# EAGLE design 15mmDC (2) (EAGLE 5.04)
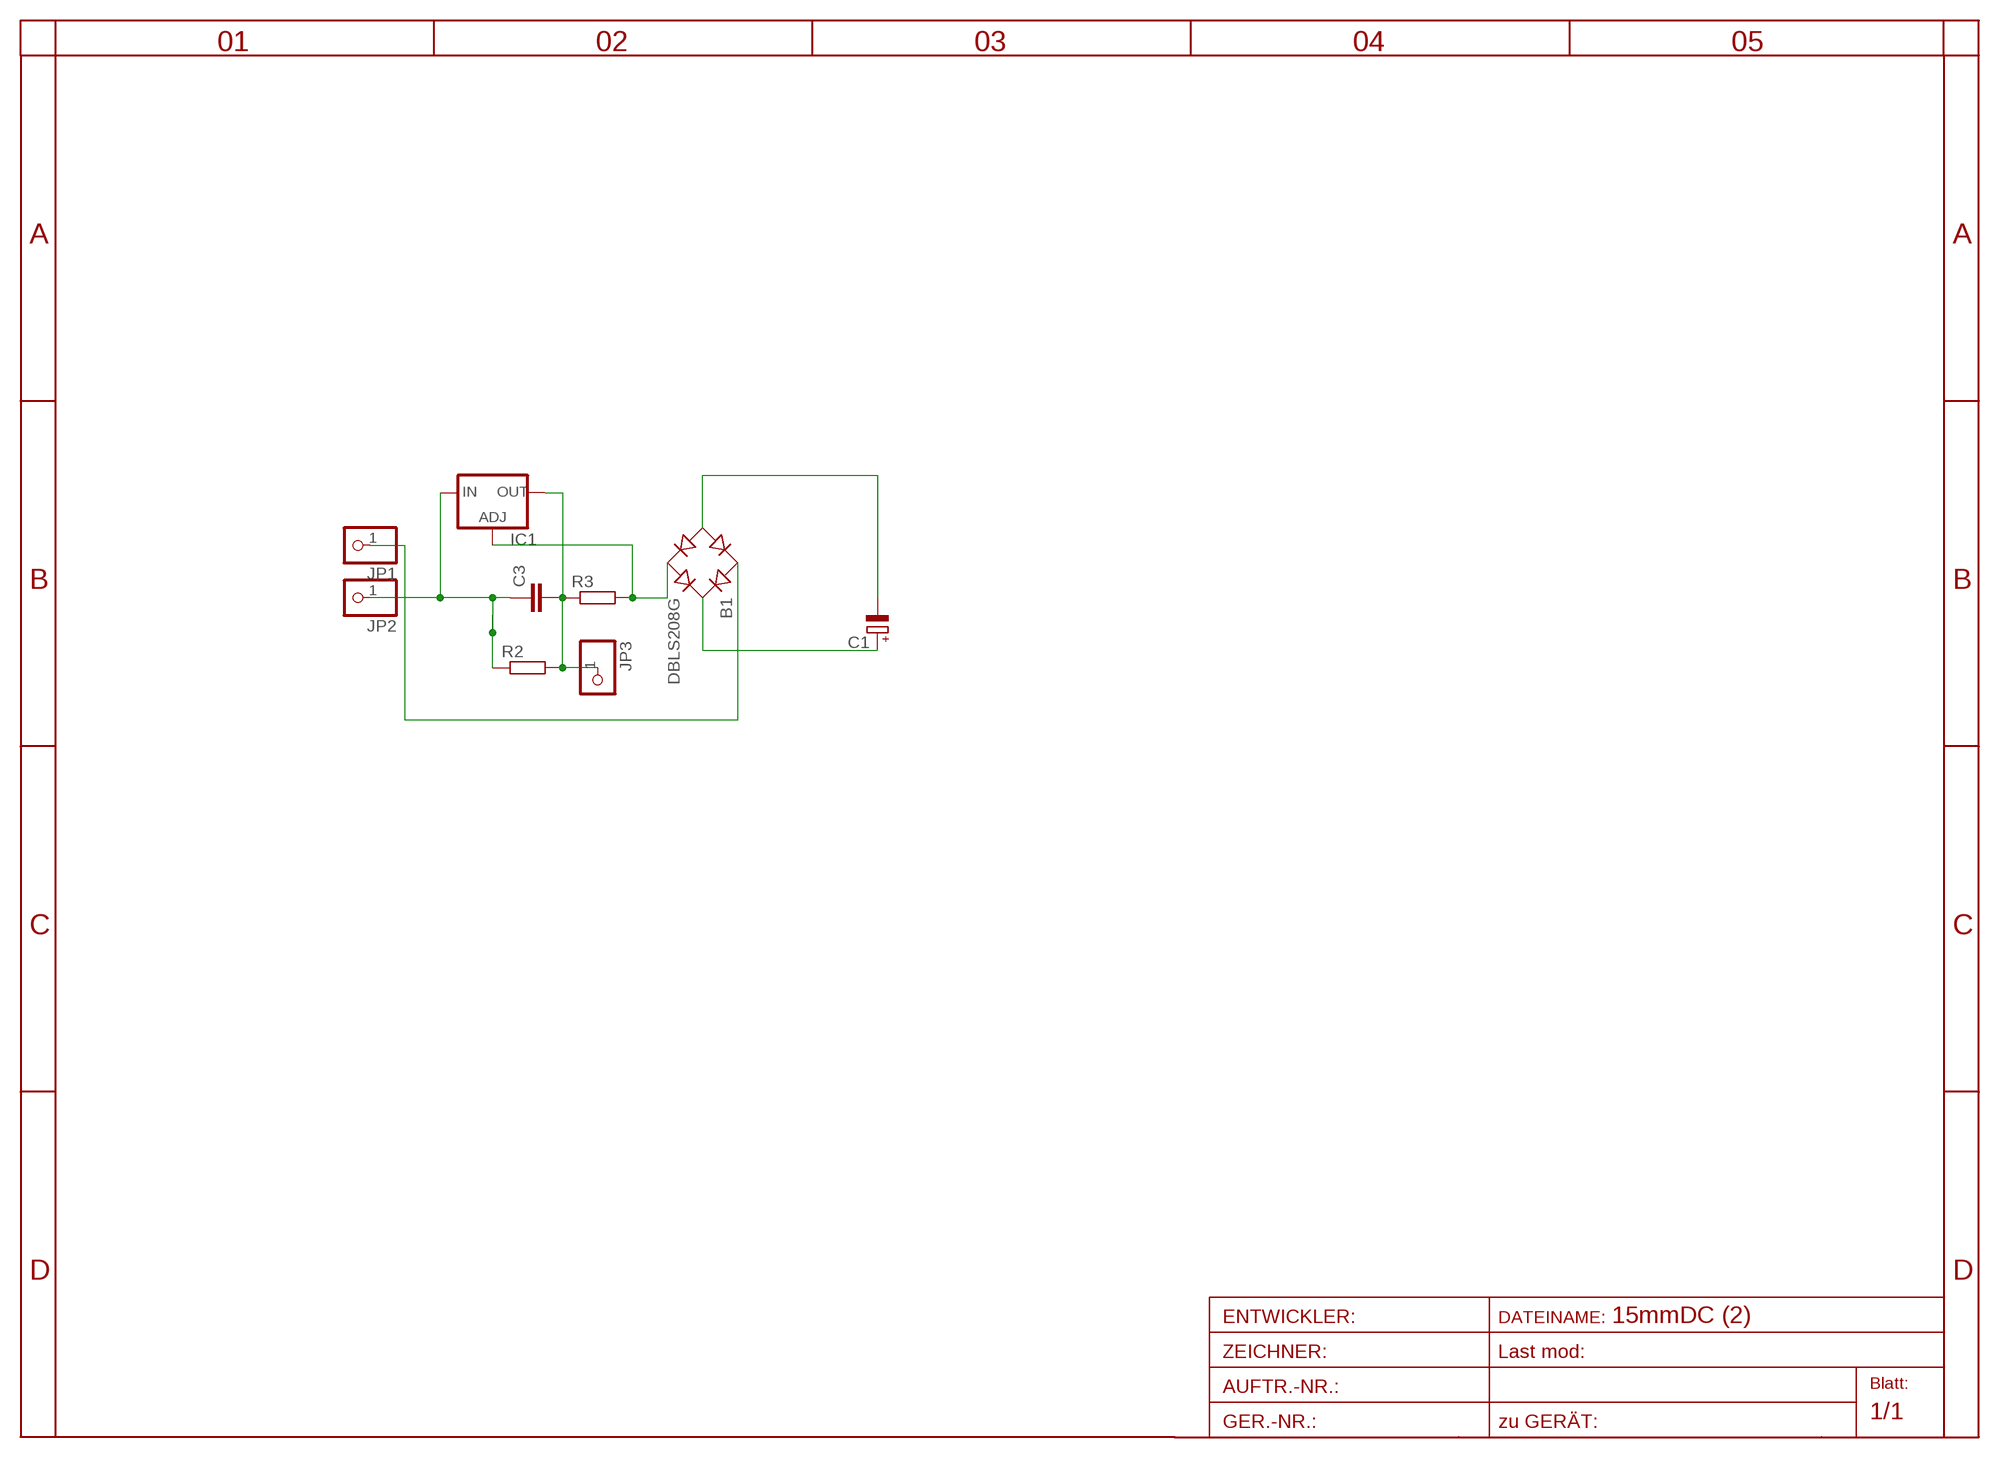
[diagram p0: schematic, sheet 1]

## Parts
B1  DBLS208G  [DBS]
C1  CPOL-EUE5-8.5  [E5-8,5]
C3  C-EU102-064X133  [C102-064X133]
IC1  LM317LZ  [317L]
JP1  PINHD-1X1  [1X01]
JP2  PINHD-1X1  [1X01]
JP3  PINHD-1X1  [1X01]
R2  R-EU_R1206  [R1206]
R3  R-EU_R1206  [R1206]

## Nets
AC+: C3.1 IC1.3(IN) JP2.1 R2.1
N$1: C3.2 IC1.2(OUT) JP3.1 R2.2 R3.1
N$2: B1.+ C1.+
N$3: B1.AC1 JP1.1
N$5: B1.AC2 IC1.1(ADJ) R3.2
N$9: B1.- C1.-

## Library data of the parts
B1 = rectifier:DB?*G: Single Phase 1.0 AMP Glass Passivated Bridge Rectifier Taiwan Semiconductor Co.,Ltd. - TSC Source: http://www.taiwansemi.com/TSCbig5/ezcatfiles/cust/img/img/db101g.pdf http://www.ts.com.tw/db/pictures/modules/PDT/PDT060207001/DBLS201G.pdf
C1 = rcl-2:CPOL-EU: POLARIZED CAPACITOR, European symbol
C3 = rcl:C-EU: CAPACITOR, European symbol
IC1 = v-reg-3:LM317L: Adjustable Voltage Regulator, 1.2V to 37V, 100mA
JP1-JP3 = pinhead:PINHD-1X1: PIN HEADER
R2 R3 = rcl:R-EU_: RESISTOR, European symbol

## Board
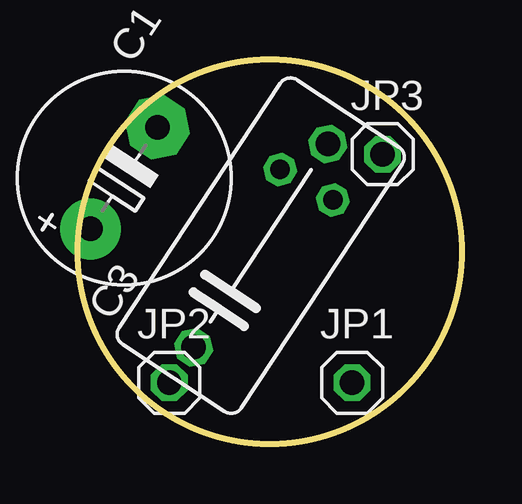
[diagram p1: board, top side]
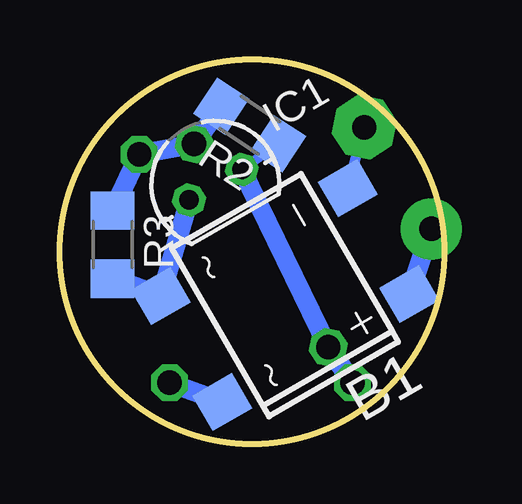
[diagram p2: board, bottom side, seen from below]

Size 16 x 16 mm. Coordinates in mm from the lower left corner, seen from the top.
Outline: circle at 8,8 radius 8
Copper layers (1*16): Top 0.035mm / dielectric 1.5mm / Bottom 0.035mm
Design rules "default *": minimum track width 10mil, minimum drill 24mil, track to track 8mil, track to pad 8mil, pad to pad 8mil, via to via 8mil, smd to smd 8mil, copper to edge 4mil, drill to drill 8mil, minimum pad ring 10mil, minimum via ring 8mil, stop-mask expansion 4mil, vias tented up to drill 0mil, thermal gap 10mil

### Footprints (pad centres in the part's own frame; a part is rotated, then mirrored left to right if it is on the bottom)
DBS = smd 1.7 x 1.9: + -2.55,-4.5; - 2.55,-4.5; AC1 -2.55,4.5; AC2 2.55,4.5
E5-8,5 = drill 1.016 pad 2.54 round: + -2.54,0 | drill 1.016 pad 2.54 octagon: - 2.54,0
C102-064X133 = drill 1.016 octagon: 1 -5.08,0; 2 5.08,0
317L = drill 0.813 octagon: 1 -1.27,0; 2 0,1.905; 3 1.27,0
1X01 = drill 1.016 octagon: 1 0,0
R1206 = smd 1.6 x 1.803: 1 -1.422,0; 2 1.422,0

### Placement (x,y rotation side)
B1  6.62,6.19 120 bottom
C1  1.93,11.07 56.6 top
C3  7.62,8.26 56.6 top
IC1  9.53,10.79 30 bottom
JP1  11.43,2.54 0 top
JP2  3.81,2.54 0 top
JP3  12.7,12.06 0 top
R2  8.1,13.28 146.6 bottom
R3  13.81,8.3 270 bottom

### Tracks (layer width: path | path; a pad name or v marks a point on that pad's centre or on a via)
AC+
  Bottom 0.406: IC1.3 R2.1
  Bottom 0.813: JP2.1 C3.1 IC1.3
N$1
  Bottom 0.406: C3.2 IC1.2
  Bottom 0.813: R2.2 C3.2 JP3.1 R3.1
N$2
  Bottom 0.813: B1.+ C1.+
N$3
  Bottom 0.813: JP1.1 B1.AC1
N$5
  Bottom 0.813: IC1.1 B1.AC2 R3.2
N$9
  Bottom 0.406: B1.- C1.-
